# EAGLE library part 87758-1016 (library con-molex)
10 Pin - 2mm Dual Row Single Wafer, Vertical T/H HDR Source: http://www.molex.com/pdm_docs/sd/877580616_sd.pdf
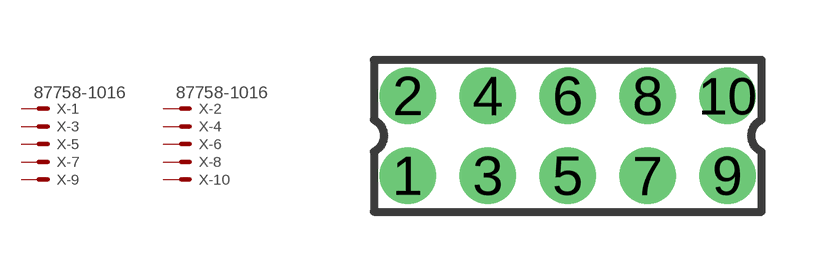
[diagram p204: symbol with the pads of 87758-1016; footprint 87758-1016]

Designator prefix X; gates -1=MV -2=MV -3=M -4=M -5=M -6=M -7=M -8=M -9=M -10=M

## 87758-1016 (MF: MOLEX; MPN: 87758-1016; OC_FARNELL: 7472340; OC_NEWARK: 59J1558)  [87758-1016]
1  -1:S  pas
2  -2:S  pas
3  -3:S  pas
4  -4:S  pas
5  -5:S  pas
6  -6:S  pas
7  -7:S  pas
8  -8:S  pas
9  -9:S  pas
10  -10:S  pas

## Footprint 87758-1016 (pad centres in mm)
10 Pin - 2mm Dual Row Single Wafer, Vertical T/H HDR Source: http://www.molex.com/pdm_docs/sd/877580616_sd.pdf
drill 0.9 pad 1.27 round: 1 -4,-1; 2 -4,1; 3 -2,-1; 4 -2,1; 5 0,-1; 6 0,1; 7 2,-1; 8 2,1; 9 4,-1; 10 4,1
